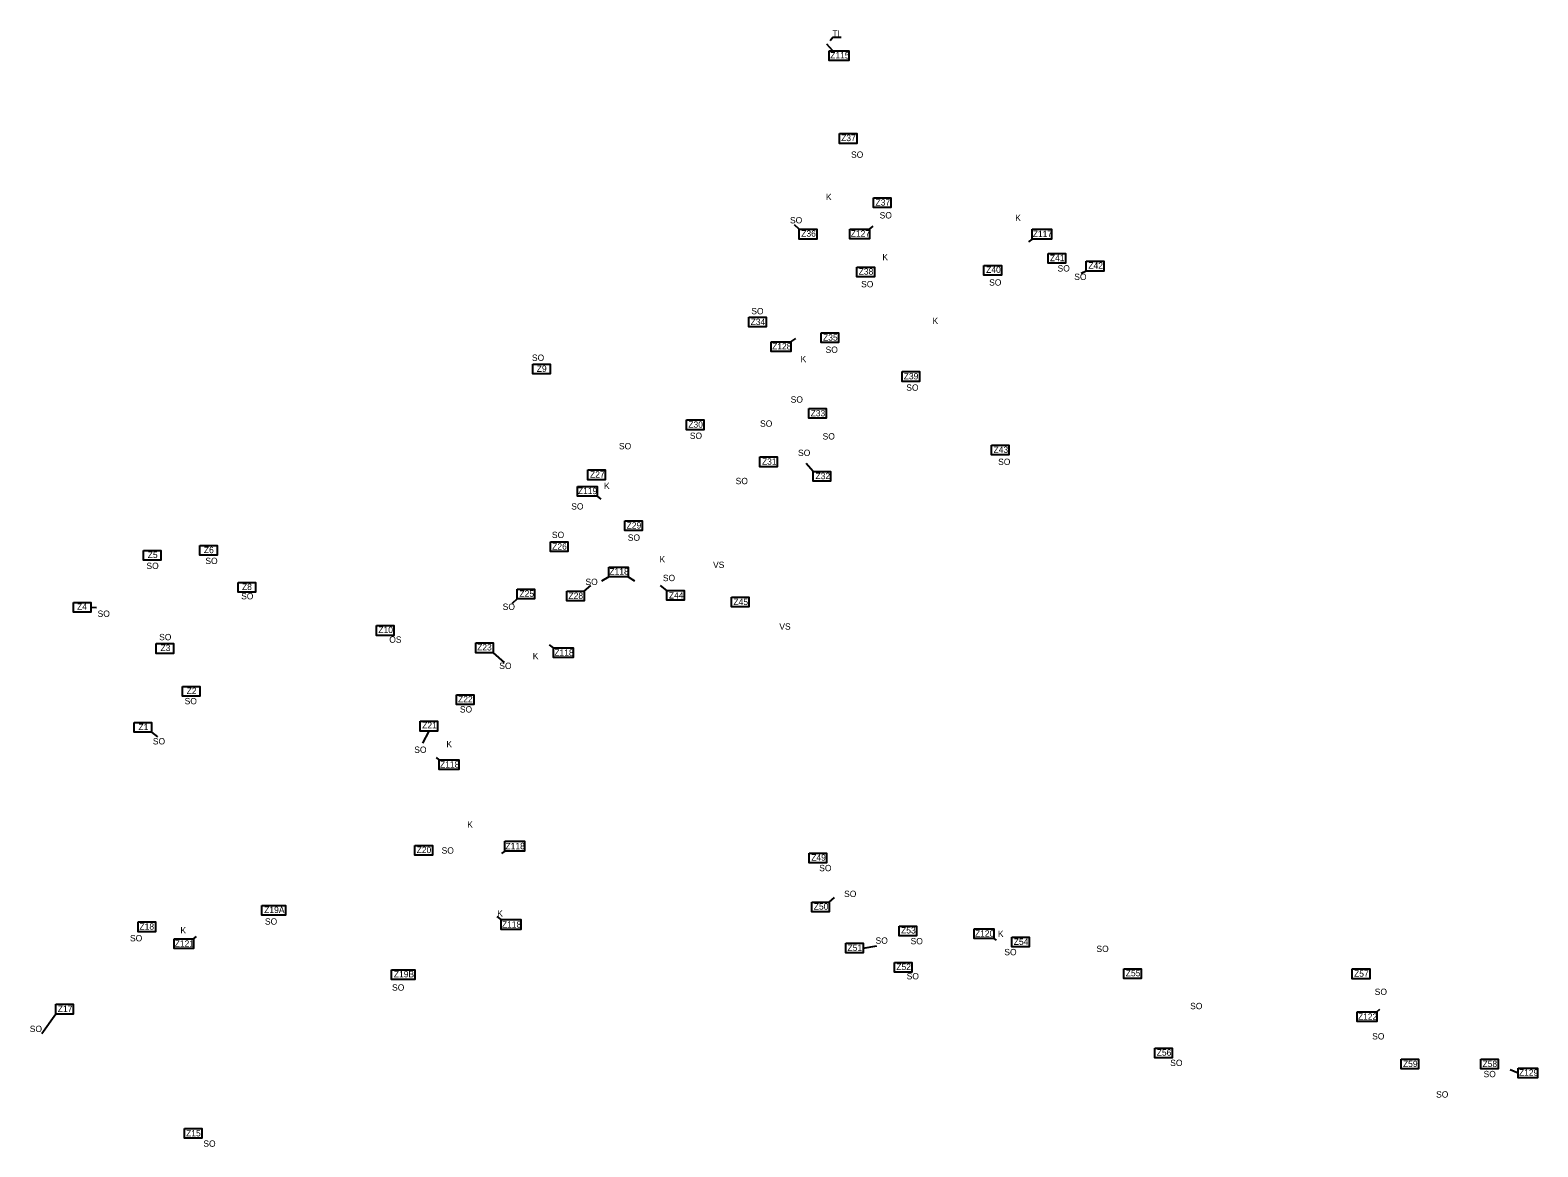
# Model space of a CAD drawing. Extents: x -443519 to -431242, y -1133468 to -1129615.
# Drawn here: x -443043 to -440666, y -1131535 to -1129775 of the extents above; entities that cross this region are included whole.
import ezdxf

# ---------------------------------------------------------------- set-up
doc = ezdxf.new("R2010")
doc.units = 0
for name, color, linetype in [('Vrstva 3', 7, 'Continuous'), ('Vrstva 4', 7, 'Continuous'), ('Vrstva 8', 7, 'Continuous')]:
    doc.layers.add(name, color=color, linetype=linetype)

msp = doc.modelspace()

# ---------------------------------------------------------------- linework, layer by layer
at = {"layer": 'Vrstva 3'}
for p, q in [((-441777.7, -1129807.7), (-441786.9, -1129797.4)), ((-441830.5, -1130088.9), (-441838, -1130081.7)), ((-441378.1, -1130154.6), (-441386.2, -1130158.4)), ((-441808.5, -1130470.4), (-441819.7, -1130457.7)), ((-442169.8, -1130659.1), (-442159.4, -1130650.4)), ((-442039.5, -1130658.1), (-442049.1, -1130650.3)), ((-442275.3, -1130671.3), (-442283.1, -1130678.3)), ((-442947.3, -1130684.5), (-442938.5, -1130684.6)), ((-442313.2, -1130756), (-442295.7, -1130771.4)), ((-442851.5, -1130881.4), (-442842.3, -1130888.4)), ((-442414.7, -1130879.5), (-442424.6, -1130898.5)), ((-441783.2, -1131148.9), (-441775.1, -1131141.9)), ((-441729.8, -1131221.4), (-441708.1, -1131217.9)), ((-443002.5, -1131325.5), (-443024.8, -1131356.8))]:
    msp.add_line(p, q, dxfattribs=at)
for points in [[(-441783.2, -1129807.7), (-441752.4, -1129807.7), (-441752.4, -1129823.1), (-441783.2, -1129823.1)], [(-441767.1, -1129938.1), (-441739.7, -1129938.1), (-441739.7, -1129953.5), (-441767.1, -1129953.5)], [(-441713.5, -1130039.3), (-441686.2, -1130039.3), (-441686.2, -1130054.7), (-441713.5, -1130054.7)], [(-441830.5, -1130088.9), (-441803.1, -1130088.9), (-441803.1, -1130104.3), (-441830.5, -1130104.3)], [(-441438.1, -1130126.8), (-441410.7, -1130126.8), (-441410.7, -1130142.2), (-441438.1, -1130142.2)], [(-441739.6, -1130148.5), (-441712.2, -1130148.5), (-441712.2, -1130163.9), (-441739.6, -1130163.9)], [(-441539.4, -1130145.7), (-441512, -1130145.7), (-441512, -1130161.1), (-441539.4, -1130161.1)], [(-441378.1, -1130139.2), (-441350.7, -1130139.2), (-441350.7, -1130154.6), (-441378.1, -1130154.6)], [(-441909.9, -1130227.3), (-441882.6, -1130227.3), (-441882.6, -1130242.7), (-441909.9, -1130242.7)], [(-441796.3, -1130252.1), (-441768.9, -1130252.1), (-441768.9, -1130267.5), (-441796.3, -1130267.5)], [(-442250.7, -1130301.4), (-442223.3, -1130301.4), (-442223.3, -1130316.8), (-442250.7, -1130316.8)], [(-441668.4, -1130313.2), (-441641, -1130313.2), (-441641, -1130328.6), (-441668.4, -1130328.6)], [(-441815.5, -1130371.3), (-441788.2, -1130371.3), (-441788.2, -1130386.7), (-441815.5, -1130386.7)], [(-442008.5, -1130389.3), (-441981.2, -1130389.3), (-441981.2, -1130404.7), (-442008.5, -1130404.7)], [(-441527.5, -1130428.9), (-441500.2, -1130428.9), (-441500.2, -1130444.3), (-441527.5, -1130444.3)], [(-441893, -1130447.6), (-441865.6, -1130447.6), (-441865.6, -1130463), (-441893, -1130463)], [(-442163.9, -1130468.1), (-442136.5, -1130468.1), (-442136.5, -1130483.5), (-442163.9, -1130483.5)], [(-441808.5, -1130470.4), (-441781.1, -1130470.4), (-441781.1, -1130485.8), (-441808.5, -1130485.8)], [(-442105.4, -1130548.2), (-442078, -1130548.2), (-442078, -1130563.6), (-442105.4, -1130563.6)], [(-442222.8, -1130581.2), (-442195.5, -1130581.2), (-442195.5, -1130596.5), (-442222.8, -1130596.5)], [(-442864.1, -1130595.1), (-442836.8, -1130595.1), (-442836.8, -1130610.4), (-442864.1, -1130610.4)], [(-442775.7, -1130587.1), (-442748.3, -1130587.1), (-442748.3, -1130602.5), (-442775.7, -1130602.5)], [(-442715, -1130645.3), (-442687.7, -1130645.3), (-442687.7, -1130660.7), (-442715, -1130660.7)], [(-442275.3, -1130655.9), (-442247.9, -1130655.9), (-442247.9, -1130671.3), (-442275.3, -1130671.3)], [(-442039.5, -1130658.1), (-442012.1, -1130658.1), (-442012.1, -1130673.5), (-442039.5, -1130673.5)], [(-442974.7, -1130676.8), (-442947.3, -1130676.8), (-442947.3, -1130692.2), (-442974.7, -1130692.2)], [(-442197.1, -1130659.1), (-442169.8, -1130659.1), (-442169.8, -1130674.5), (-442197.1, -1130674.5)], [(-441937.3, -1130668.5), (-441909.9, -1130668.5), (-441909.9, -1130683.9), (-441937.3, -1130683.9)], [(-442497.1, -1130713.3), (-442469.7, -1130713.3), (-442469.7, -1130728.7), (-442497.1, -1130728.7)], [(-442844.2, -1130741.8), (-442816.9, -1130741.8), (-442816.9, -1130757.2), (-442844.2, -1130757.2)], [(-442340.6, -1130740.6), (-442313.2, -1130740.6), (-442313.2, -1130756), (-442340.6, -1130756)], [(-442802.8, -1130809.3), (-442775.4, -1130809.3), (-442775.4, -1130824.7), (-442802.8, -1130824.7)], [(-442370.9, -1130822.5), (-442343.6, -1130822.5), (-442343.6, -1130837.9), (-442370.9, -1130837.9)], [(-442878.9, -1130866.1), (-442851.5, -1130866.1), (-442851.5, -1130881.4), (-442878.9, -1130881.4)], [(-442428.4, -1130864.1), (-442401, -1130864.1), (-442401, -1130879.5), (-442428.4, -1130879.5)], [(-442436.4, -1131059.8), (-442409, -1131059.8), (-442409, -1131075.2), (-442436.4, -1131075.2)], [(-441815, -1131072), (-441787.6, -1131072), (-441787.6, -1131087.4), (-441815, -1131087.4)], [(-442677.7, -1131154.3), (-442640.5, -1131154.3), (-442640.5, -1131169.7), (-442677.7, -1131169.7)], [(-441810.6, -1131148.9), (-441783.2, -1131148.9), (-441783.2, -1131164.3), (-441810.6, -1131164.3)], [(-442872.7, -1131180.4), (-442845.3, -1131180.4), (-442845.3, -1131195.7), (-442872.7, -1131195.7)], [(-441673.2, -1131186.9), (-441645.8, -1131186.9), (-441645.8, -1131202.2), (-441673.2, -1131202.2)], [(-441495.6, -1131204.2), (-441468.2, -1131204.2), (-441468.2, -1131219.6), (-441495.6, -1131219.6)], [(-441757.2, -1131213.7), (-441729.8, -1131213.7), (-441729.8, -1131229.1), (-441757.2, -1131229.1)], [(-441680.5, -1131244), (-441653.2, -1131244), (-441653.2, -1131259.4), (-441680.5, -1131259.4)], [(-442473.2, -1131255.7), (-442436.5, -1131255.7), (-442436.5, -1131271.1), (-442473.2, -1131271.1)], [(-441319, -1131254), (-441291.6, -1131254), (-441291.6, -1131269.4), (-441319, -1131269.4)], [(-440958.8, -1131254.3), (-440931.4, -1131254.3), (-440931.4, -1131269.7), (-440958.8, -1131269.7)], [(-443002.5, -1131310.1), (-442975.2, -1131310.1), (-442975.2, -1131325.5), (-443002.5, -1131325.5)], [(-441270.2, -1131379), (-441242.8, -1131379), (-441242.8, -1131394.4), (-441270.2, -1131394.4)], [(-440882, -1131396.5), (-440854.6, -1131396.5), (-440854.6, -1131411.9), (-440882, -1131411.9)], [(-440756.3, -1131396.5), (-440728.9, -1131396.5), (-440728.9, -1131411.9), (-440756.3, -1131411.9)], [(-442799.7, -1131505.6), (-442772.3, -1131505.6), (-442772.3, -1131521), (-442799.7, -1131521)]]:
    msp.add_lwpolyline(points, close=True, dxfattribs=at)
at = {"layer": 'Vrstva 4'}
msp.add_lwpolyline([(-441764.3, -1129786.7), (-441777.7, -1129786.7), (-441781.9, -1129791.9)], dxfattribs=at)
at = {"layer": 'Vrstva 8'}
for p, q in [((-441720.1, -1130088.6), (-441714.3, -1130084)), ((-441463.6, -1130104.2), (-441469.4, -1130108.5)), ((-441844, -1130266.2), (-441836.1, -1130260.9)), ((-442149.3, -1130509.6), (-442143.6, -1130514.2)), ((-442131, -1130636.5), (-442142.2, -1130643.1)), ((-442100.3, -1130636.5), (-442090.5, -1130642.7)), ((-442217.8, -1130748.4), (-442224.2, -1130743.6)), ((-442398, -1130924.7), (-442402.3, -1130921.1)), ((-442294.8, -1131068.6), (-442299.8, -1131072.4)), ((-442300.3, -1131176.7), (-442306.7, -1131171.9)), ((-442785.3, -1131206.9), (-442780.8, -1131203.4)), ((-441523.9, -1131206.4), (-441520.2, -1131209.2)), ((-440920.2, -1131322), (-440915.5, -1131317.9)), ((-440697.5, -1131418.4), (-440709.9, -1131413.3))]:
    msp.add_line(p, q, dxfattribs=at)
for points in [[(-441750.9, -1130088.6), (-441720.1, -1130088.6), (-441720.1, -1130104), (-441750.9, -1130104)], [(-441463.6, -1130088.8), (-441432.8, -1130088.8), (-441432.8, -1130104.2), (-441463.6, -1130104.2)], [(-441463.6, -1130088.8), (-441432.8, -1130088.8), (-441432.8, -1130104.2), (-441463.6, -1130104.2)], [(-441874.8, -1130266.2), (-441844, -1130266.2), (-441844, -1130281.6), (-441874.8, -1130281.6)], [(-442180.1, -1130494.2), (-442149.3, -1130494.2), (-442149.3, -1130509.6), (-442180.1, -1130509.6)], [(-442131, -1130621.1), (-442100.3, -1130621.1), (-442100.3, -1130636.5), (-442131, -1130636.5)], [(-442217.8, -1130748.4), (-442187, -1130748.4), (-442187, -1130763.8), (-442217.8, -1130763.8)], [(-442398, -1130924.7), (-442367.2, -1130924.7), (-442367.2, -1130940.1), (-442398, -1130940.1)], [(-442294.8, -1131053.2), (-442264, -1131053.2), (-442264, -1131068.6), (-442294.8, -1131068.6)], [(-442300.3, -1131176.7), (-442269.5, -1131176.7), (-442269.5, -1131192.1), (-442300.3, -1131192.1)], [(-441554.7, -1131191), (-441523.9, -1131191), (-441523.9, -1131206.4), (-441554.7, -1131206.4)], [(-442816.1, -1131206.9), (-442785.3, -1131206.9), (-442785.3, -1131222.3), (-442816.1, -1131222.3)], [(-440951, -1131322), (-440920.2, -1131322), (-440920.2, -1131337.4), (-440951, -1131337.4)], [(-440697.5, -1131410.7), (-440666.8, -1131410.7), (-440666.8, -1131426.1), (-440697.5, -1131426.1)]]:
    msp.add_lwpolyline(points, close=True, dxfattribs=at)

# ---------------------------------------------------------------- texts
at = {"layer": 'Vrstva 3'}
for s, p in [('Z115', (-441781.8, -1129819.7)), ('Z37', (-441764.6, -1129949.9)), ('Z37', (-441710.4, -1130051.5)), ('Z36', (-441827.5, -1130100.6)), ('Z41', (-441435.5, -1130139.1)), ('Z38', (-441736.9, -1130160.4)), ('Z40', (-441536, -1130157.5)), ('Z42', (-441374.9, -1130151)), ('Z34', (-441907.3, -1130239.7)), ('Z35', (-441793.1, -1130264.3)), ('Z9', (-442244.4, -1130313.5)), ('Z39', (-441665.9, -1130325.4)), ('Z30', (-442005.5, -1130401.6)), ('Z33', (-441812.7, -1130383.7)), ('Z43', (-441524.3, -1130441.2)), ('Z31', (-441889.4, -1130459.9)), ('Z27', (-442160.4, -1130480.1)), ('Z32', (-441805, -1130482.6)), ('Z29', (-442102.7, -1130560.4)), ('Z26', (-442220.1, -1130593.6)), ('Z5', (-442857.7, -1130606.9)), ('Z6', (-442769.2, -1130599.2)), ('Z8', (-442709.1, -1130657.3)), ('Z25', (-442271.7, -1130668)), ('Z4', (-442969.1, -1130688.5)), ('Z28', (-442194.4, -1130671.3)), ('Z44', (-442036.1, -1130670.7)), ('Z45', (-441934.4, -1130681)), ('Z10', (-442494.1, -1130725)), ('Z3', (-442837.5, -1130753.5)), ('Z23', (-442338.4, -1130752.5)), ('Z2', (-442796.3, -1130821.1)), ('Z22', (-442368.4, -1130834.2)), ('Z1', (-442872.3, -1130878.1)), ('Z21', (-442425, -1130875.4)), ('Z20', (-442433.8, -1131071.9)), ('Z49', (-441811.7, -1131083.8)), ('Z19A', (-442674.1, -1131166.3)), ('Z50', (-441807.7, -1131160.9)), ('Z18', (-442870.7, -1131192.5)), ('Z53', (-441670.1, -1131198.5)), ('Z51', (-441754.6, -1131226.1)), ('Z54', (-441492.5, -1131216.4)), ('Z52', (-441677.6, -1131256)), ('Z19B', (-442469.7, -1131267.7)), ('Z55', (-441315.9, -1131266)), ('Z57', (-440956, -1131266.7)), ('Z17', (-442999.4, -1131322.1)), ('Z56', (-441267.1, -1131391.1)), ('Z59', (-440878.9, -1131409)), ('Z58', (-440753.5, -1131409)), ('Z15', (-442797.2, -1131518.3))]:
    msp.add_text(s, height=10, dxfattribs=at).set_placement(p)
at = {"layer": 'Vrstva 4'}
for s, p in [('TI', (-441778.4, -1129785.1)), ('SO', (-441749, -1129976.2)), ('K', (-441788.5, -1130042.9)), ('SO', (-441703.9, -1130071.8)), ('SO', (-441845.2, -1130079.6)), ('K', (-441490.1, -1130075.8)), ('K', (-441699.6, -1130137.8)), ('SO', (-441423.4, -1130155.4)), ('SO', (-441397.1, -1130168.7)), ('SO', (-441733.1, -1130180.3)), ('SO', (-441531.3, -1130177.6)), ('SO', (-441906.2, -1130222.8)), ('K', (-441620.6, -1130238.2)), ('SO', (-441789.1, -1130283.6)), ('SO', (-442252, -1130296.2)), ('K', (-441828.5, -1130298.3)), ('SO', (-441661.9, -1130343.3)), ('SO', (-441844.1, -1130362.1)), ('SO', (-441892.4, -1130400)), ('SO', (-442003.1, -1130419.2)), ('SO', (-441793.8, -1130420.1)), ('SO', (-442114.8, -1130435.6)), ('SO', (-441832.5, -1130446.1)), ('SO', (-441517.1, -1130460.2)), ('K', (-442138.4, -1130498.1)), ('SO', (-441930.9, -1130490.5)), ('SO', (-442190.1, -1130530.5)), ('SO', (-442220.5, -1130575.4)), ('SO', (-442100.9, -1130579.7)), ('SO', (-442766.8, -1130616.4)), ('K', (-442050.9, -1130613.8)), ('SO', (-442859.7, -1130624.2)), ('SO', (-442045.6, -1130643.3)), ('VS', (-441966.5, -1130622.5)), ('SO', (-442167.6, -1130649.4)), ('SO', (-442710.4, -1130672)), ('SO', (-442298.1, -1130688.6)), ('SO', (-442936.7, -1130699.6)), ('SO', (-442839.7, -1130736.4)), ('VS', (-441862, -1130719.8)), ('OS', (-442476.9, -1130740.4)), ('SO', (-442303.5, -1130781.7)), ('K', (-442250.7, -1130766.3)), ('SO', (-442799.5, -1130837.3)), ('SO', (-442365.6, -1130850.3)), ('SO', (-442849.6, -1130900.6)), ('K', (-442386.9, -1130905.2)), ('SO', (-442437.5, -1130913.9)), ('K', (-442354, -1131031.8)), ('SO', (-442394.4, -1131072.7)), ('SO', (-441799.1, -1131100.4)), ('SO', (-441759.9, -1131141.1)), ('SO', (-442672.9, -1131184.6)), ('K', (-442306.7, -1131171.9)), ('SO', (-442885.6, -1131210.9)), ('K', (-442806.1, -1131198.5)), ('SO', (-441710.3, -1131214.7)), ('K', (-441517.4, -1131204)), ('SO', (-441655.1, -1131215.5)), ('SO', (-441507.3, -1131232.8)), ('SO', (-441362.1, -1131227.7)), ('SO', (-441661.3, -1131270.8)), ('SO', (-442472.5, -1131288.6)), ('SO', (-440923.4, -1131295.4)), ('SO', (-441214.4, -1131317.8)), ('SO', (-443043.6, -1131353.8)), ('SO', (-440927.5, -1131365.5)), ('SO', (-441245.8, -1131407.4)), ('SO', (-440751.9, -1131425)), ('SO', (-440826.7, -1131457.1)), ('SO', (-442770, -1131534.6))]:
    msp.add_text(s, height=10, dxfattribs=at).set_placement(p)
at = {"layer": 'Vrstva 8'}
for s, p in [('Z127', (-441749.5, -1130100.6)), ('Z117', (-441462.5, -1130101.2)), ('Z128', (-441873.4, -1130278.2)), ('Z119', (-442179.6, -1130506.2)), ('Z118', (-442129.9, -1130632.9)), ('Z118', (-442216.7, -1130760.9)), ('Z118', (-442396.9, -1130937.1)), ('Z118', (-442293.7, -1131065.7)), ('Z118', (-442299.3, -1131189.2)), ('Z120', (-441553.6, -1131203.5)), ('Z121', (-442815.1, -1131219.3)), ('Z122', (-440949.9, -1131334.5)), ('Z129', (-440696.1, -1131422.7))]:
    msp.add_text(s, height=10, dxfattribs=at).set_placement(p)

doc.saveas('drawing.dxf')
